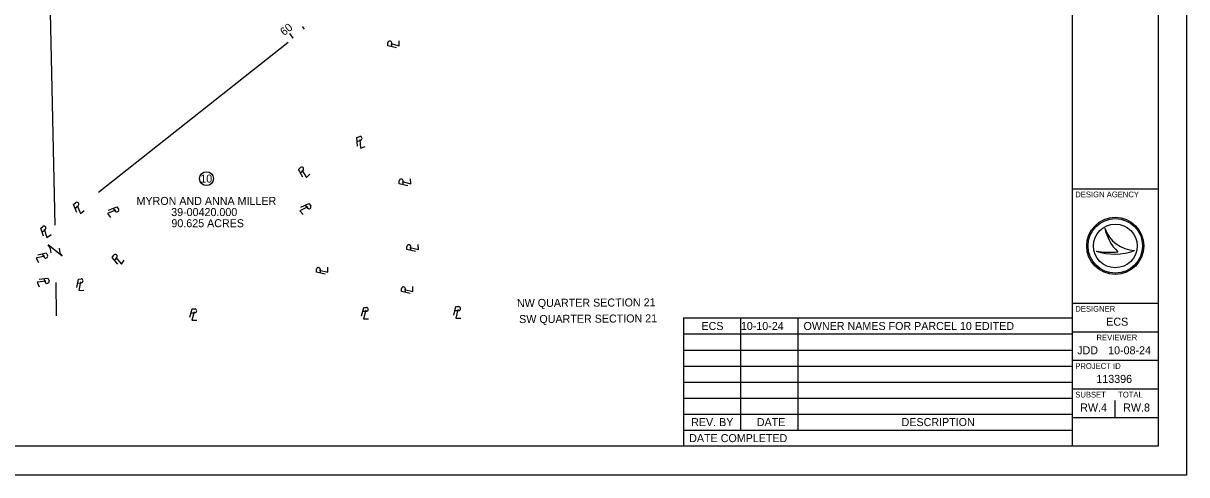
# Model space of a CAD drawing. Extents: x 2180380 to 2187180, y 367894 to 372294.
# Drawn here: x 2183109 to 2187180, y 367894 to 369473 of the extents above; entities that cross this region are included whole.
import ezdxf

# ---------------------------------------------------------------- set-up
doc = ezdxf.new("R2010")
doc.units = 0
for name, color, linetype in [('Default', 7, 'Continuous'), ('DR_X_Elev_Flow', 7, 'Continuous'), ('PV_X_COP', 7, 'Continuous'), ('RD_X_Cells', 7, 'Continuous'), ('SN_X_Public', 7, 'Continuous'), ('SV_X_Control_Cells_Found', 7, 'Continuous'), ('SV_X_Random_Point', 7, 'Continuous'), ('SV_X_Shot_Marker', 7, 'Continuous'), ('UT_X_Telecom_Cells', 7, 'Continuous')]:
    doc.layers.add(name, color=color, linetype=linetype)

msp = doc.modelspace()

# ---------------------------------------------------------------- linework, layer by layer
at = {"layer": 'Default'}
msp.add_circle((2183750.4, 368929.5), 24.3, dxfattribs=at)
at = {"layer": 'DR_X_Elev_Flow'}
for p, q in [((2186893.4, 368756.3), (2186893.4, 368756.3)), ((2186863.3, 368676.3), (2186863.3, 368676.3)), ((2186929.9, 368694.4), (2186929.9, 368694.4)), ((2186997.3, 368678.1), (2186997.3, 368678.1)), ((2186929.9, 368094.4), (2186929.9, 368154.4))]:
    msp.add_line(p, q, dxfattribs=at)
for radius in [100, 95.4, 95.4, 76.4]:
    msp.add_circle((2186929.9, 368694.4), radius, dxfattribs=at)
for centre, radius, start, end in [((2187003.1, 368793.9), 116, 198.9257, 198.9319), ((2187049.2, 368788.4), 159.1, 191.6379, 191.6421), ((2187003.1, 368793.9), 116, 198.9319, 267.1657), ((2187049.2, 368788.4), 159.1, 191.6421, 226.0947), ((2186927.8, 368868.4), 202.6, 251.4576, 290.0832), ((2186909.5, 368925.3), 253.2, 259.4964, 259.4995), ((2186927.8, 368868.4), 202.6, 251.4527, 251.4576), ((2186909.5, 368925.3), 253.2, 259.4995, 276.6672)]:
    msp.add_arc(centre, radius, start, end, dxfattribs=at)
at = {"layer": 'PV_X_COP'}
msp.add_line((2183372.7, 368881.9), (2184035.8, 369406.7), dxfattribs=at)
at = {"layer": 'RD_X_Cells'}
for p, q in [((2186779.9, 367994.4), (2186779.9, 372194.4)), ((2186779.9, 368894.4), (2187079.9, 368894.4)), ((2186779.9, 368494.4), (2187079.9, 368494.4)), ((2186779.9, 368394.4), (2187079.9, 368394.4)), ((2186779.9, 368294.4), (2187079.9, 368294.4)), ((2186779.9, 368194.4), (2187079.9, 368194.4)), ((2186779.9, 368094.4), (2187079.9, 368094.4))]:
    msp.add_line(p, q, dxfattribs=at)
msp.add_lwpolyline([(2180679.9, 372194.4), (2187079.9, 372194.4), (2187079.9, 367994.4), (2180679.9, 367994.4)], close=True, dxfattribs=at)
at = {"layer": 'SN_X_Public'}
for p, q in [((2184093.3, 369452.4), (2184085.9, 369461.8)), ((2184054.2, 369421.3), (2184041.7, 369436.9))]:
    msp.add_line(p, q, dxfattribs=at)
at = {"layer": 'SV_X_Control_Cells_Found'}
for p, q in [((2183195.4, 369878.1), (2183219.4, 368766.9)), ((2183222.8, 368566.2), (2183224.7, 368450.4))]:
    msp.add_line(p, q, dxfattribs=at)
at = {"layer": 'SV_X_Random_Point'}
msp.add_lwpolyline([(2180379.9, 367894.4), (2187179.9, 367894.4), (2187179.9, 372294.4), (2180379.9, 372294.4)], close=True, dxfattribs=at)
at = {"layer": 'SV_X_Shot_Marker'}
for p, q in [((2185419.2, 368442.4), (2185419.2, 367994.4)), ((2185419.2, 368442.4), (2186779.9, 368442.4)), ((2185619.2, 368442.4), (2185619.2, 368050.4)), ((2185819.2, 368442.4), (2185819.2, 368050.4)), ((2185419.2, 368386.4), (2186779.9, 368386.4)), ((2185419.2, 368330.4), (2186779.9, 368330.4)), ((2185419.2, 368274.4), (2186779.9, 368274.4)), ((2185419.2, 368218.4), (2186779.9, 368218.4)), ((2185419.2, 368162.4), (2186779.9, 368162.4)), ((2185419.2, 368106.4), (2186779.9, 368106.4)), ((2185419.2, 368050.4), (2186779.9, 368050.4)), ((2186779.9, 367994.4), (2186779.9, 367994.4))]:
    msp.add_line(p, q, dxfattribs=at)
at = {"layer": 'UT_X_Telecom_Cells'}
for p, q in [((2184398.6, 369391.1), (2184398.3, 369404.1)), ((2184404.6, 369399.2), (2184404.6, 369399.2)), ((2184277.7, 369059.6), (2184289.9, 369064)), ((2184287.3, 369056.4), (2184287.3, 369056.4)), ((2184079.2, 368949.4), (2184088.2, 368958.6)), ((2184089.2, 368950.7), (2184089.2, 368950.7)), ((2184438.7, 368908.5), (2184438.4, 368921.4)), ((2184444.7, 368916.6), (2184444.7, 368916.6)), ((2183290.9, 368826.5), (2183301.2, 368834.4)), ((2184095.5, 368836.5), (2184103.9, 368826.7)), ((2183301.1, 368826.5), (2183301.1, 368826.5)), ((2183423.2, 368815.8), (2183423.2, 368815.8)), ((2183423.3, 368826), (2183431.1, 368815.7)), ((2184095.9, 368826.4), (2184095.9, 368826.4)), ((2183175.1, 368743.7), (2183185.8, 368751.1)), ((2183185.3, 368743.1), (2183185.3, 368743.1)), ((2183244.9, 368658), (2183196.9, 368698)), ((2183220.9, 368678), (2183220.9, 368678)), ((2184465.5, 368678.8), (2184465.3, 368691.7)), ((2184471.6, 368686.9), (2184471.6, 368686.9)), ((2183174.1, 368656.6), (2183174.1, 368656.6)), ((2183175.8, 368666.7), (2183181.9, 368655.2)), ((2183429.5, 368643.2), (2183437.1, 368653.7)), ((2183439.3, 368646.1), (2183439.3, 368646.1)), ((2184149, 368599.2), (2184148.8, 368612.2)), ((2184155.1, 368607.4), (2184155.1, 368607.4)), ((2183178.7, 368570.2), (2183178.7, 368570.2)), ((2183181.6, 368579.9), (2183186.3, 368567.8)), ((2183299.4, 368564.7), (2183312.4, 368565.6)), ((2183307.9, 368559), (2183307.9, 368559)), ((2184446.6, 368531.5), (2184446.3, 368544.4)), ((2184452.7, 368539.6), (2184452.7, 368539.6)), ((2184296.7, 368465.8), (2184309.6, 368465.8)), ((2184619.6, 368468.3), (2184632.5, 368468.3)), ((2183696.4, 368460.7), (2183709.3, 368460.7)), ((2183704.4, 368454.5), (2183704.4, 368454.5)), ((2184304.7, 368459.6), (2184304.7, 368459.6)), ((2184627.6, 368462.1), (2184627.6, 368462.1))]:
    msp.add_line(p, q, dxfattribs=at)
for points in [[(2184414.6, 369387.2), (2184384.8, 369394.4), (2184384.6, 369404.8)], [(2184395, 369401.7), (2184424.7, 369394.4), (2184424.3, 369411.9)], [(2184279, 369043.2), (2184276.5, 369073.8), (2184286.3, 369077.2)], [(2184286.6, 369066.4), (2184289, 369035.9), (2184305.5, 369041.7)], [(2184087.6, 368935.2), (2184071.9, 368961.6), (2184079.1, 368968.9)], [(2184084.2, 368959.4), (2184099.8, 368933), (2184112, 368945.5)], [(2184454.7, 368904.6), (2184424.9, 368911.8), (2184424.7, 368922.1)], [(2184435.1, 368919.1), (2184464.8, 368911.8), (2184464.4, 368929.2)], [(2183297.3, 368811.4), (2183285.5, 368839.7), (2183293.7, 368845.9)], [(2183297.4, 368835.7), (2183309.1, 368807.4), (2183322.9, 368818)], [(2183408.1, 368819.6), (2183436.4, 368831.4), (2183442.6, 368823.2)], [(2184105, 368830.6), (2184077.4, 368817.4), (2184088.7, 368804.1)], [(2184080.6, 368829.4), (2184108.2, 368842.7), (2184115, 368834.9)], [(2183432.4, 368819.5), (2183404.1, 368807.9), (2183414.7, 368794)], [(2183180.7, 368728.2), (2183170.3, 368757), (2183178.8, 368762.9)], [(2183182, 368752.5), (2183192.3, 368723.7), (2183206.7, 368733.7)], [(2183159.8, 368662.8), (2183189.6, 368670), (2183194.5, 368660.9)], [(2184481.5, 368674.9), (2184451.7, 368682.1), (2184451.5, 368692.4)], [(2184461.9, 368689.4), (2184491.7, 368682.1), (2184491.3, 368699.5)], [(2183183.8, 368658.8), (2183154, 368651.8), (2183162.3, 368636.4)], [(2183440, 368630.5), (2183420.5, 368654.1), (2183426.5, 368662.5)], [(2183433, 368653.8), (2183452.5, 368630.2), (2183462.6, 368644.4)], [(2184165, 368595.4), (2184135.2, 368602.6), (2184135, 368612.9)], [(2184145.4, 368609.8), (2184175.2, 368602.5), (2184174.8, 368620)], [(2183188.6, 368571.2), (2183158.2, 368568), (2183164.4, 368551.7)], [(2183165.3, 368578.2), (2183195.7, 368581.5), (2183199.4, 368571.8)], [(2183296.4, 368548.5), (2183302.1, 368578.6), (2183312.4, 368579.4)], [(2183309.8, 368568.8), (2183304.1, 368538.8), (2183321.5, 368540)], [(2184462.6, 368527.6), (2184432.8, 368534.8), (2184432.6, 368545.1)], [(2184443, 368542.1), (2184472.7, 368534.8), (2184472.4, 368552.2)], [(2183692.2, 368444.8), (2183700, 368474.4), (2183710.3, 368474.4)], [(2183707.1, 368464.1), (2183699.1, 368434.5), (2183716.6, 368434.5)], [(2184292.5, 368449.9), (2184300.3, 368479.6), (2184310.6, 368479.5)], [(2184307.4, 368469.2), (2184299.4, 368439.6), (2184316.9, 368439.6)], [(2184615.4, 368452.4), (2184623.2, 368482.1), (2184633.5, 368482)], [(2184630.3, 368471.7), (2184622.3, 368442.1), (2184639.8, 368442.1)]]:
    msp.add_lwpolyline(points, dxfattribs=at)
for centre, radius, start, end in [((2184391.4, 369403.9), 6.9, 1.6735, 172.5306), ((2184287.6, 369070.5), 6.9, 289.9182, 100.7753), ((2184083.3, 368963.4), 6.9, 316.0377, 126.8948), ((2184431.5, 368921.2), 6.9, 1.6704, 172.5275), ((2183297, 368839.9), 6.9, 307.8737, 118.7308), ((2184109.1, 368831.2), 6.9, 221.0503, 31.9075), ((2183436.6, 368819.9), 6.9, 217.8527, 28.7098), ((2183181.8, 368756.7), 6.9, 305.2357, 116.0928), ((2183153.9, 368666.4), 53.4, 3.6945, 36.337), ((2183287.9, 368689.7), 53.4, 183.6945, 216.337), ((2184458.4, 368691.5), 6.9, 1.6704, 172.5275), ((2183188, 368658.6), 6.9, 208.7404, 19.5975), ((2183431.5, 368657.7), 6.9, 324.8715, 135.7287), ((2184141.9, 368612), 6.9, 1.6704, 172.5275), ((2183192.7, 368570.4), 6.9, 201.4677, 12.3248), ((2183311.8, 368572.5), 6.9, 274.6068, 85.4639), ((2184439.4, 368544.2), 6.9, 1.6704, 172.5275), ((2183709.3, 368467.6), 6.9, 270.471, 81.3281), ((2184309.6, 368472.7), 6.9, 270.471, 81.3281), ((2184632.5, 368475.2), 6.9, 270.471, 81.3281)]:
    msp.add_arc(centre, radius, start, end, dxfattribs=at)

# ---------------------------------------------------------------- texts
at = {"layer": 'Default'}
for s, p in [('10', (2183728.7, 368915.8)), ('MYRON AND ANNA MILLER', (2183505.6, 368837.7)), ('39-00420.000', (2183626.9, 368798.7)), ('90.625 ACRES', (2183627.6, 368759.7))]:
    msp.add_text(s, height=28, dxfattribs=at).set_placement(p)
for s, p in [('NW QUARTER SECTION 21', (2184836.7, 368480.5)), ('SW QUARTER SECTION 21', (2184844.4, 368424.5))]:
    msp.add_text(s, height=28, rotation=0.3234, dxfattribs=at).set_placement(p)
at = {"layer": 'DR_X_Elev_Flow'}
for s, height, p in [('DESIGN AGENCY', 20, (2186789.9, 368864.4)), ('DESIGNER', 20, (2186789.9, 368464.4)), ('ECS', 28, (2186898.3, 368415.4)), ('REVIEWER', 20, (2186864.2, 368364.4)), ('JDD', 28, (2186796.7, 368315.4)), ('10-08-24', 28, (2186904.9, 368315.4)), ('PROJECT ID', 20, (2186789.9, 368264.4)), ('113396', 28, (2186863.7, 368215.4)), ('SUBSET', 20, (2186789.9, 368164.4)), ('TOTAL', 20, (2186939.9, 368164.4)), ('RW.4', 28, (2186807.3, 368115.4)), ('RW.8', 28, (2186957.6, 368115.4))]:
    msp.add_text(s, height=height, dxfattribs=at).set_placement(p)
at = {"layer": 'SN_X_Public'}
msp.add_text('60', height=28, rotation=38.4323, dxfattribs=at).set_placement((2184021.8, 369427.5))
at = {"layer": 'SV_X_Shot_Marker'}
for s, p in [('ECS', (2185482.1, 368400.4)), ('10-10-24', (2185620, 368400.4)), ('OWNER NAMES FOR PARCEL 10 EDITED       ', (2185839.2, 368400.4)), ('REV. BY', (2185446, 368064.4)), ('DATE', (2185675.8, 368064.4)), ('DESCRIPTION', (2186182.3, 368064.4)), ('DATE COMPLETED', (2185439.2, 368008.4))]:
    msp.add_text(s, height=28, dxfattribs=at).set_placement(p)

doc.saveas('drawing.dxf')
